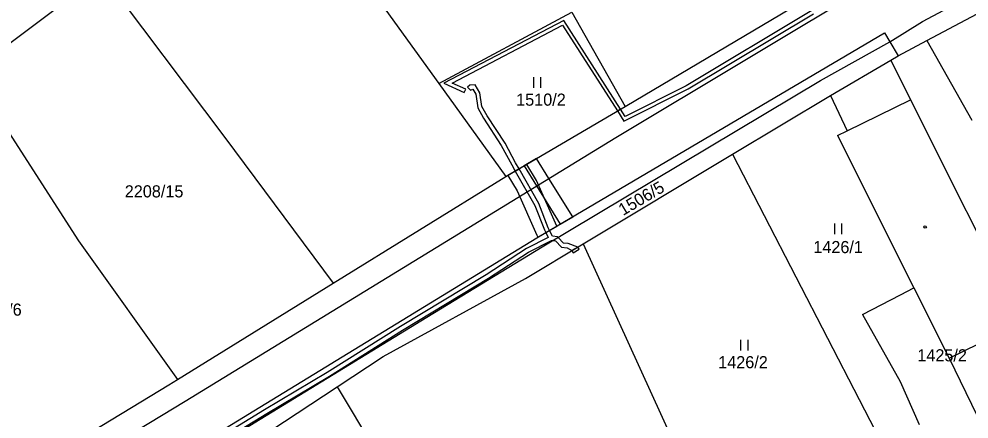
# Model space of a CAD drawing. Extents: x -785744 to -782822, y -1067550 to -1063910.
# Drawn here: x -784600.3 to -784467.1, y -1065557.7 to -1065501.6 of the extents above; entities that cross this region are included whole.
import ezdxf

# ---------------------------------------------------------------- set-up
doc = ezdxf.new("R2010")
doc.units = 0
for name, color, linetype in [('Hranice parcel', 7, 'Continuous'), ('Parcelní čísla', 7, 'Continuous'), ('Vnitřní kresba', 7, 'Continuous'), ('Věcná břemena k části', 7, 'Continuous'), ('Značky budov', 7, 'Continuous'), ('Značky kultur', 7, 'Continuous')]:
    doc.layers.add(name, color=color, linetype=linetype)

msp = doc.modelspace()

# ---------------------------------------------------------------- linework, layer by layer
at = {"layer": 'Hranice parcel'}
for p, q in [((-784474.84, -1065539.31), (-784469.88, -1065549.22)), ((-784469.88, -1065549.22), (-784465.21, -1065558.82))]:
    msp.add_line(p, q, dxfattribs=at)
for points in [[(-784581.99, -1065454.44), (-784541.45, -1065510.67)], [(-784473.04, -1065504.64), (-784447.2, -1065490.88)], [(-784515.32, -1065513.87), (-784481.8, -1065493.94)], [(-784633, -1065528.56), (-784588.68, -1065495.28)], [(-784588.68, -1065495.28), (-784571.41, -1065518.25)], [(-784541.45, -1065510.67), (-784522.78, -1065500.65)], [(-784522.78, -1065500.65), (-784515.32, -1065513.87)], [(-784527.67, -1065532.32), (-784478.95, -1065503.53)], [(-784478.95, -1065503.53), (-784478.21, -1065504.79)], [(-784487.94, -1065510.24), (-784478.21, -1065504.79)], [(-784478.21, -1065504.79), (-784477.03, -1065506.79)], [(-784477.03, -1065506.79), (-784473.04, -1065504.64)], [(-784473.04, -1065504.64), (-784466.71, -1065515.78)], [(-784486.54, -1065512.32), (-784478.08, -1065507.36)], [(-784478.08, -1065507.36), (-784477.03, -1065506.79)], [(-784541.45, -1065510.67), (-784532.03, -1065523.73)], [(-784526.93, -1065533.58), (-784487.94, -1065510.24)], [(-784500.25, -1065520.56), (-784486.54, -1065512.32)], [(-784486.54, -1065512.32), (-784484.21, -1065517.28)], [(-784604.27, -1065513.59), (-784591.93, -1065532.74)], [(-784518.58, -1065515.81), (-784515.32, -1065513.87)], [(-784532.03, -1065523.73), (-784518.58, -1065515.81)], [(-784485.56, -1065517.94), (-784484.21, -1065517.28)], [(-784571.41, -1065518.25), (-784556.23, -1065538.7)], [(-784485.56, -1065517.94), (-784474.84, -1065539.31)], [(-784521.22, -1065533.17), (-784500.25, -1065520.56)], [(-784500.25, -1065520.56), (-784478.09, -1065563.61)], [(-784556.23, -1065538.7), (-784532.03, -1065523.73)], [(-784620.05, -1065588.83), (-784527.67, -1065532.32)], [(-784591.93, -1065532.74), (-784578.06, -1065552.21)], [(-784529.28, -1065538.02), (-784521.22, -1065533.17)], [(-784521.22, -1065533.17), (-784497.35, -1065585.52)], [(-784543.1, -1065543.47), (-784526.93, -1065533.58)], [(-784549.23, -1065548.99), (-784529.28, -1065538.02)], [(-784578.06, -1065552.21), (-784556.23, -1065538.7)], [(-784476.74, -1065540.3), (-784474.84, -1065539.31)], [(-784482.04, -1065543.07), (-784476.74, -1065540.3)], [(-784619.29, -1065590.08), (-784543.1, -1065543.47)], [(-784482.04, -1065543.07), (-784476.78, -1065552.46)], [(-784469.88, -1065549.22), (-784459.67, -1065544.2)], [(-784555.69, -1065553.24), (-784549.23, -1065548.99)], [(-784605.95, -1065569.14), (-784579.25, -1065552.95)], [(-784579.25, -1065552.95), (-784578.06, -1065552.21)], [(-784572.38, -1065564.2), (-784555.69, -1065553.24)], [(-784555.69, -1065553.24), (-784534.76, -1065588.21)], [(-784476.78, -1065552.46), (-784474.11, -1065558.52)]]:
    msp.add_lwpolyline(points, dxfattribs=at)
at = {"layer": 'Vnitřní kresba'}
for points in [[(-784473.63, -1065501.97), (-784448.33, -1065488.45)], [(-784516.64, -1065518.22), (-784479.97, -1065496.19)], [(-784478.21, -1065504.79), (-784473.63, -1065501.97)], [(-784478.08, -1065507.36), (-784475.32, -1065512.95)], [(-784484.21, -1065517.28), (-784475.32, -1065512.95)], [(-784475.32, -1065512.95), (-784459.67, -1065544.2)], [(-784576.98, -1065555.24), (-784516.64, -1065518.22)], [(-784625.93, -1065584.89), (-784576.98, -1065555.24)]]:
    msp.add_lwpolyline(points, dxfattribs=at)
at = {"layer": 'Věcná břemena k části'}
for points in [[(-784489.15, -1065500.43), (-784506.74, -1065511)], [(-784506.48, -1065511.42), (-784488.93, -1065500.87)], [(-784523.93, -1065501.83), (-784540.72, -1065510.61)], [(-784539.58, -1065510.59), (-784524.11, -1065502.49)], [(-784524.11, -1065502.49), (-784516.4, -1065514.51)], [(-784515.97, -1065514.26), (-784523.93, -1065501.83)], [(-784540.72, -1065510.61), (-784537.87, -1065511.93)], [(-784537.66, -1065511.47), (-784539.58, -1065510.59)], [(-784537.87, -1065511.93), (-784537.66, -1065511.47)], [(-784537.06, -1065510.9), (-784537.41, -1065511.16)], [(-784537.41, -1065511.16), (-784536.98, -1065511.58)], [(-784536.35, -1065510.83), (-784537.06, -1065510.9)], [(-784536.98, -1065511.58), (-784536.67, -1065511.47)], [(-784536.67, -1065511.47), (-784536.25, -1065512.16)], [(-784535.67, -1065511.96), (-784536.35, -1065510.83)], [(-784535.39, -1065513.89), (-784535.67, -1065511.96)], [(-784515.48, -1065515.95), (-784506.48, -1065511.42)], [(-784506.74, -1065511), (-784515.3, -1065515.29)], [(-784536.25, -1065512.16), (-784535.97, -1065514.09)], [(-784535.97, -1065514.09), (-784535.16, -1065515.51)], [(-784534.64, -1065515.19), (-784535.39, -1065513.89)], [(-784515.97, -1065514.26), (-784516.4, -1065514.51)], [(-784516.4, -1065514.51), (-784515.97, -1065514.26)], [(-784516.4, -1065514.51), (-784515.48, -1065515.95)], [(-784515.3, -1065515.29), (-784515.97, -1065514.26)], [(-784535.16, -1065515.51), (-784532.67, -1065519.35)], [(-784532.15, -1065519.05), (-784534.64, -1065515.19)], [(-784532.67, -1065519.35), (-784531.21, -1065522.08)], [(-784530.69, -1065521.78), (-784532.15, -1065519.05)], [(-784527.73, -1065521.2), (-784529.48, -1065522.23)], [(-784526.01, -1065523.97), (-784527.73, -1065521.2)], [(-784529.1, -1065522.01), (-784531.77, -1065523.57)], [(-784531.21, -1065522.08), (-784530.71, -1065522.95)], [(-784530.71, -1065522.95), (-784530.19, -1065522.65)], [(-784530.19, -1065522.65), (-784530.71, -1065522.95)], [(-784530.19, -1065522.65), (-784530.69, -1065521.78)], [(-784527.41, -1065527.5), (-784530.19, -1065522.65)], [(-784529.48, -1065522.23), (-784527.75, -1065525.03)], [(-784527.73, -1065524.28), (-784529.1, -1065522.01)], [(-784531.77, -1065523.57), (-784530.47, -1065525.71)], [(-784530.71, -1065522.95), (-784527.95, -1065527.76)], [(-784522.66, -1065529.36), (-784526.01, -1065523.97)], [(-784527.75, -1065525.03), (-784524.42, -1065530.4)], [(-784524.88, -1065530.67), (-784527.73, -1065524.28)], [(-784530.47, -1065525.71), (-784527.69, -1065531.94)], [(-784527.95, -1065527.76), (-784526.63, -1065531.17)], [(-784526.09, -1065530.93), (-784527.41, -1065527.5)], [(-784527.69, -1065531.94), (-784527.53, -1065532.24), (-784524.88, -1065530.67)], [(-784524.42, -1065530.4), (-784522.66, -1065529.36)], [(-784526.63, -1065531.17), (-784526.42, -1065531.58)], [(-784525.91, -1065531.28), (-784526.42, -1065531.58)], [(-784526.42, -1065531.58), (-784525.91, -1065531.28)], [(-784526.42, -1065531.58), (-784526.09, -1065532.25)], [(-784525.91, -1065531.28), (-784526.09, -1065530.93)], [(-784525.49, -1065532.1), (-784525.91, -1065531.28)], [(-784526.09, -1065532.25), (-784529.14, -1065533.79)], [(-784528.84, -1065534.31), (-784525.63, -1065532.69)], [(-784525.63, -1065532.69), (-784525.47, -1065532.71)], [(-784524.78, -1065532.17), (-784525.49, -1065532.1)], [(-784525.47, -1065532.71), (-784525.06, -1065532.75)], [(-784525.06, -1065532.75), (-784524.23, -1065533.63)], [(-784524.71, -1065532.25), (-784524.78, -1065532.17)], [(-784523.95, -1065533.05), (-784524.71, -1065532.25)], [(-784523.28, -1065533.13), (-784523.95, -1065533.05)], [(-784521.95, -1065533.61), (-784523.28, -1065533.13)], [(-784529.14, -1065533.79), (-784534.78, -1065537.49)], [(-784534.46, -1065537.99), (-784528.84, -1065534.31)], [(-784524.23, -1065533.63), (-784523.42, -1065533.71)], [(-784523.42, -1065533.71), (-784522.78, -1065534.11)], [(-784521.95, -1065533.61), (-784522.78, -1065534.11), (-784522.6, -1065534.41)], [(-784522.78, -1065534.11), (-784522.55, -1065533.97)], [(-784522.6, -1065534.41), (-784521.77, -1065533.92), (-784521.95, -1065533.61)], [(-784522.55, -1065533.97), (-784522.3, -1065533.82)], [(-784522.3, -1065533.82), (-784521.95, -1065533.61)], [(-784534.78, -1065537.49), (-784546.82, -1065544.77)], [(-784546.5, -1065545.29), (-784534.46, -1065537.99)], [(-784546.82, -1065544.77), (-784557.08, -1065551.2)], [(-784556.76, -1065551.72), (-784546.5, -1065545.29)], [(-784557.08, -1065551.2), (-784565.85, -1065556.45)], [(-784565.53, -1065556.97), (-784556.76, -1065551.72)], [(-784565.85, -1065556.45), (-784571.43, -1065559.88)], [(-784571.07, -1065560.36), (-784565.53, -1065556.97)]]:
    msp.add_lwpolyline(points, dxfattribs=at)
at = {"layer": 'Značky budov'}
msp.add_circle((-784473.27, -1065530.79), 0.175, dxfattribs=at)
at = {"layer": 'Značky kultur'}
for p, q in [((-784528.12, -1065511.27), (-784528.12, -1065509.77)), ((-784527.12, -1065511.27), (-784527.12, -1065509.77)), ((-784485.92, -1065531.79), (-784485.92, -1065530.29)), ((-784484.92, -1065531.79), (-784484.92, -1065530.29)), ((-784499.09, -1065548.11), (-784499.09, -1065546.61)), ((-784498.09, -1065548.11), (-784498.09, -1065546.61))]:
    msp.add_line(p, q, dxfattribs=at)

# ---------------------------------------------------------------- texts
at = {"layer": 'Parcelní čísla'}
for s, p in [('1510/2', (-784530.59, -1065513.77)), ('2208/15', (-784585.45, -1065526.64)), ('1426/1', (-784488.94, -1065534.46)), ('2209/6', (-784606.85, -1065543.24)), ('1425/2', (-784474.36, -1065549.65)), ('1426/2', (-784502.27, -1065550.62))]:
    msp.add_text(s, height=1.7, dxfattribs=at).set_placement(p)
msp.add_text('1506/5', height=1.7, rotation=30.6507, dxfattribs=at).set_placement((-784515.61, -1065529.26))

doc.saveas('drawing.dxf')
